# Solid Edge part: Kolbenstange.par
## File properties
Username: bmolnar
Dokumentum tartalom típus: 0
Author: bmolnar
Last saved by: bmolnar
Revision: 85
Sűrűség: 0,000 kg/m^3
Pontosság: 0,990
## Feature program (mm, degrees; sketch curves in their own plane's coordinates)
base feature "unnamed BaseFeature 1"
sketch for "unnamed Protrusion 1" plane through (57, 0, 0) normal (1, 0, 0) x-axis (0, -1, 0)
  circle centre (0, 0) radius 40
extrude "unnamed Protrusion 1" add finite 12 along +normal
thread "unnamed Thread 1"
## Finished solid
Body 1: solid body, 17 faces, 23 edges, 8 vertices.
  Faces by surface: plane 8, cylinder 4, torus 3, cone 2
  Edges by curve: circle 13, line 6, ellipse 2, intersection 2
Bounding box of the edges (mm; curved faces can reach further): 124.000 x 80.000 x 80.000, from (-55, -40, -40) to (69, 40, 40).
Cylindrical faces by radius (mm): R6.75 x1, R8 x1, R10 x1, R40 x1
Conical faces (half-angle, radius in mm at the cone's reference point): 20 deg R7.4 x1, 60 deg R7.475 x1
Toroidal faces (ring radius, tube radius in mm): R7.15 r0.4 x2, R8.2 r1.8 x1
Planar faces by outward normal: +x 1, +y 1, -x 3, -y 1, oblique 2
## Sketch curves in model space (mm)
circle centre (57, 0, 0) radius 40
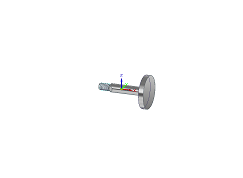
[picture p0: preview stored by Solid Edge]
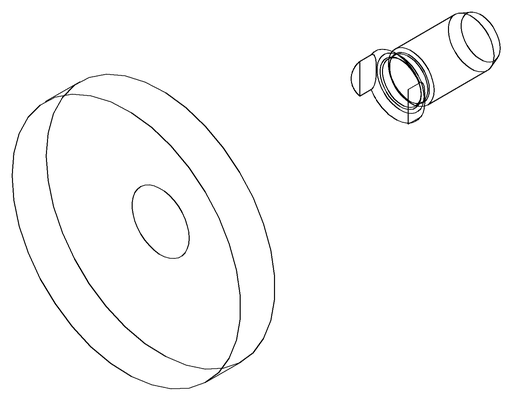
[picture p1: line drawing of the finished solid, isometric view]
